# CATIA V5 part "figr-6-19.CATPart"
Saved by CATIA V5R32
Part number: Part1
Bounding box of the stored display mesh (mm): x 0 to 150, y -70 to 70, z -150 to 69.804
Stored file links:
  D:\PROJECTS\Project 2022\CATIA V5 6R 2022\Resources\Part Files\c06_catia_v5_6r2022_prt\figr-6-19.CATPart
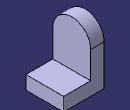
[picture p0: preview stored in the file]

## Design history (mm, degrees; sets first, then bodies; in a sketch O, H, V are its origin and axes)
Body1 (main body)
  Sketch1 on yz-plane, origin (0, 0, 0), H (0, 1, 0), V (0, 0, 1)
    arc A1 centre (0, 0) radius 70 from (70, 0) to (-70, 0) ccw
    point P1 (70, 0)
    point P2 (-70, 0)
    line L1 (-70, 0) -> (-70, -150)
    line L2 (-70, -150) -> (70, -150)
    line L3 (70, -150) -> (70, 0)
    construction circle A2 centre (0, 0) radius 37.5
    radius A1 = 70
    radius A2 = 37.5
    distance O L2 = 150
    coincidence: P1 H, P2 H
    tangency: L1 A1, L3 A1
    horizontal: L2 H
  Pad1: profile Sketch1, direction (1, 0, 0), length 50
  Sketch2 on face of Pad1, origin (50, 0, 0), H (0, 1, 0), V (0, 0, 1)
    line L1 (-70, -150) -> (70, -150)
    line L2 (70, -150) -> (70, -100)
    line L3 (70, -100) -> (-70, -100)
    line L4 (-70, -100) -> (-70, -150)
    reference projected line E1 (-70, -150) -> (70, -150) from edge [face of Pad1 | face of Pad1]
    reference projected line E2 (-70, 0) -> (-70, -150) from edge [face of Pad1 | face of Pad1]
    reference projected line E3 (70, -150) -> (70, 0) from edge [face of Pad1 | face of Pad1]
    length L2 = 50
    horizontal: L1 H, L3 H
    vertical: L2 V, L4 V
    coincidence: L1 E1, E2 L4, L2 E3
  Pad2: profile Sketch2, direction (1, 0, 0), length 100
